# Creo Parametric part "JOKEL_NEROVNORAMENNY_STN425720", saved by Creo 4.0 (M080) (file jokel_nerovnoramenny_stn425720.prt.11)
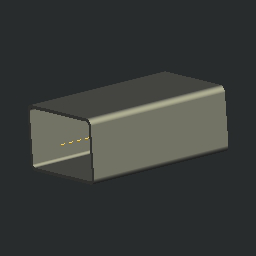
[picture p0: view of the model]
Units: Custom; MM, KILOGRAM, SECS
Materials in the file: OCEL_N

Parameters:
  NORMINFO = "Quadrat- und Rechteck-Hohlprofile (kaltgefertigt, geschweißt)"
  BENENNUNG = "Hohlprofil"
  N_T = "0"
  B_T = "2"
  HERSTELLER = "."
  KATEGORIE = "0"
  DESIGNER = "."
  DATE = "."
  FORMAT = "."
  MOD_INDEX_1 = "."
  MOD_INDEX_2 = "."
  MOD_INDEX_3 = "."
  MOD_INDEX_4 = "."
  MOD_INDEX_5 = "."
  MOD_INDEX_6 = "."
  MOD_INDEX_7 = "."
  MOD_INDEX_8 = "."
  MOD_NOTE_1 = "."
  MOD_NOTE_2 = "."
  MOD_NOTE_3 = "."
  MOD_NOTE_4 = "."
  MOD_NOTE_5 = "."
  MOD_NOTE_6 = "."
  MOD_NOTE_7 = "."
  MOD_NOTE_8 = "."
  MOD_DATE_1 = "."
  MOD_DATE_2 = "."
  MOD_DATE_3 = "."
  MOD_DATE_4 = "."
  MOD_DATE_5 = "."
  MOD_DATE_6 = "."
  MOD_DATE_7 = "."
  MOD_DATE_8 = "."
  MOD_NAME_1 = "."
  MOD_NAME_2 = "."
  MOD_NAME_3 = "."
  MOD_NAME_4 = "."
  MOD_NAME_5 = "."
  MOD_NAME_6 = "."
  MOD_NAME_7 = "."
  MOD_NAME_8 = "."
  NAZOV = "JOKEL_NEROVNORAMENNY_STN425720"
  ROZMER = "TR4HR 40x60x2-100"
  NORMA = "STN 42 5720"
  HMOTNOST_HR = "."
  MATERIAL_ZAKL = "."
  PTC_MATERIAL_NAME = "OCEL_N"

Other parameters: L, B, H, GEWICHT, T, HMOTNOST, RADIUS, HUSTOTA, HMOTNOST_1, D19, D20, D23, D24

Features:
  1. datum plane "Y-Y"
  2. datum plane "X-X"
  3. datum plane "Z-Z"
  4. coordinate system
  5. datum axis
  6. datum axis
  7. datum axis
  8. protrusion
  9. curve

Other named items: ZZ, XX, YY, CS0

Named dimensions: adius, Hoehe, Dicke, Laenge, Breite, laenge_nf

Layers: BEZUG, BEZUGSACHSEN, PLAZIERUNG, PROFIL_NEUTRALE_FASER

Notes: Hohlprofil | HP 40x40x2x100 DIN 59411 | Gewicht:  | 0.231 | Widerstandsmoment-Wx:  |  cm³ | Widerstandsmoment-Wy:  |  cm³ | Querschnittsflaeche-A:  |  cm²

Family table entries: GENERIC, JOKEL_TR4HR_40X20X2, JOKEL_NEROVNORAMENNY_STN425720, value(d_val), 2/4, value(s_val), 2.030, 31.340, 32.14, value(i_val), JOKEL_TR4HR_40X20X2_6, JOKEL_NEROVNORAMENNY_STN425720, !/D, 2/4, "2.400, 31.570, 32.68, JOKEL_TR4HR_50X30X2, JOKEL_NEROVNORAMENNY_STN425720, !/I, 2/>, "3.810, 32.860, 32.94, JOKEL_TR4HR_50X30X3_2, JOKEL_NEROVNORAMENNY_STN425720, !/I, 2/>, "5.350, 33.950, 34.45, JOKEL_TR4HR_50X30X4, JOKEL_NEROVNORAMENNY_STN425720, !/I, 2/>, "6.100, 34.460, 35.35, JOKEL_TR4HR_60X40X2, JOKEL_NEROVNORAMENNY_STN425720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

Surfaces: 10 plane, 8 cylinder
